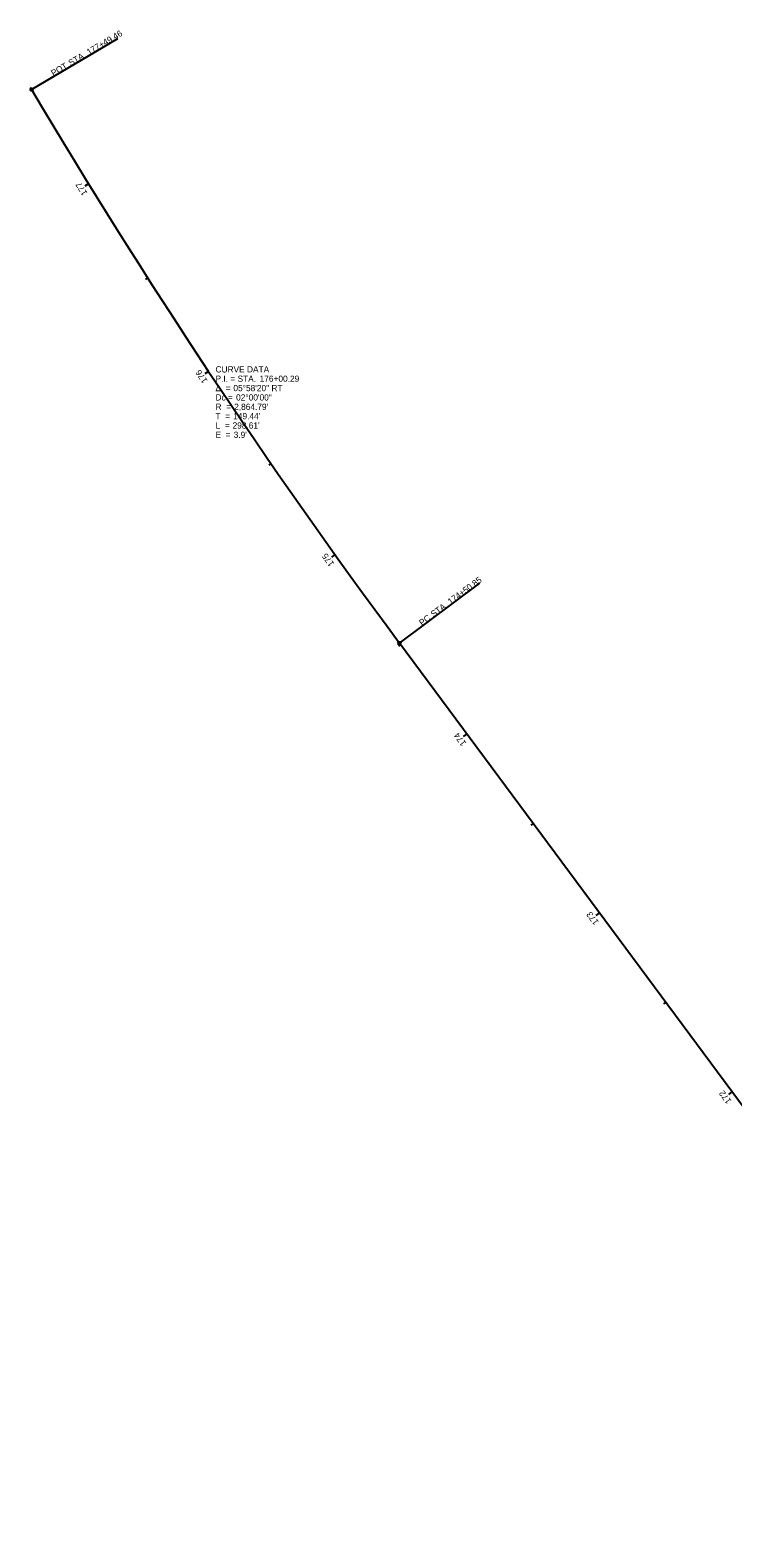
# Model space of a CAD drawing. Extents: x 142407 to 143428, y 484951 to 486303.
# Drawn here: x 142407 to 142723, y 485626 to 486303 of the extents above; entities that cross this region are included whole.
import ezdxf

# ---------------------------------------------------------------- set-up
doc = ezdxf.new("R2010")
doc.units = 0
for name, color, linetype in [('GE_X_Alignment', 7, 'Continuous'), ('GE_X_Alignment_1000_Curve_Data', 7, 'Continuous'), ('GE_X_Alignment_1000_Stations', 7, 'Continuous'), ('GE_X_Alignment_100_Curve_Data', 7, 'Continuous'), ('GE_X_Alignment_100_Stations', 7, 'Continuous'), ('GE_X_Alignment_500_Curve_Data', 7, 'Continuous'), ('GE_X_Alignment_500_Stations', 7, 'Continuous'), ('SV_P_Control_Cells_Set', 7, 'Continuous')]:
    doc.layers.add(name, color=color, linetype=linetype)

msp = doc.modelspace()

# ---------------------------------------------------------------- linework, layer by layer
at = {"layer": 'GE_X_Alignment'}
msp.add_line((143201.27, 485180.76), (142573.01, 486028.27), dxfattribs=at)
msp.add_arc((144872.98, 487736.23), 2864.79, 210.62525, 216.59745, dxfattribs=at)
at = {"layer": 'GE_X_Alignment_1000_Stations'}
for p, q in [((142407.78, 486276.85), (142446.51, 486299.77)), ((142544.04, 486067.98), (142543.07, 486067.28)), ((142573.01, 486028.27), (142609.13, 486055.1))]:
    msp.add_line(p, q, dxfattribs=at)
for centre in [(142407.78, 486276.85), (142573.01, 486028.27)]:
    msp.add_circle(centre, 0.6, dxfattribs=at)
at = {"layer": 'GE_X_Alignment_100_Stations'}
for p, q in [((142407.78, 486276.85), (142446.51, 486299.77)), ((142433.35, 486234.5), (142431.64, 486233.45)), ((142459.93, 486192.15), (142458.92, 486191.51)), ((142487.24, 486150.27), (142485.58, 486149.17)), ((142515.28, 486108.88), (142514.3, 486108.2)), ((142544.04, 486067.98), (142542.42, 486066.81)), ((142573.01, 486028.27), (142609.13, 486055.1)), ((142573.51, 486027.59), (142572.55, 486026.87)), ((142603.29, 485987.42), (142601.68, 485986.23)), ((142633.07, 485947.25), (142632.1, 485946.54)), ((142662.84, 485907.09), (142661.23, 485905.89)), ((142692.62, 485866.92), (142691.65, 485866.2)), ((142722.39, 485826.75), (142720.79, 485825.56))]:
    msp.add_line(p, q, dxfattribs=at)
for centre in [(142407.78, 486276.85), (142573.01, 486028.27)]:
    msp.add_circle(centre, 0.6, dxfattribs=at)
at = {"layer": 'GE_X_Alignment_500_Stations'}
for p, q in [((142407.78, 486276.85), (142446.51, 486299.77)), ((142433.35, 486234.5), (142432.32, 486233.87)), ((142487.24, 486150.27), (142486.24, 486149.61)), ((142544.04, 486067.98), (142542.42, 486066.81)), ((142573.01, 486028.27), (142609.13, 486055.1)), ((142603.29, 485987.42), (142602.33, 485986.71)), ((142662.84, 485907.09), (142661.88, 485906.37)), ((142722.39, 485826.75), (142721.43, 485826.04))]:
    msp.add_line(p, q, dxfattribs=at)
for centre in [(142407.78, 486276.85), (142573.01, 486028.27)]:
    msp.add_circle(centre, 0.6, dxfattribs=at)
at = {"layer": 'SV_P_Control_Cells_Set'}
for p, q in [((142408.45, 486276.18), (142407.11, 486277.51)), ((142407.11, 486276.18), (142408.45, 486277.51)), ((142573.67, 486027.61), (142572.34, 486028.94)), ((142572.34, 486027.61), (142573.67, 486028.94))]:
    msp.add_line(p, q, dxfattribs=at)

# ---------------------------------------------------------------- texts
at = {"layer": 'GE_X_Alignment_1000_Curve_Data'}
for s, p in [('CURVE DATA', (142490.39, 486149.76)), ('Δ  = ', (142490.39, 486141.36)), ('P.I. = STA. ', (142490.39, 486145.56)), ('05°58\'20" RT', (142498.42, 486141.36)), ('176+00.29', (142510.21, 486145.56)), ('Dc = ', (142490.39, 486137.16)), ('02°00\'00"', (142499.63, 486137.16)), ('T  = ', (142490.39, 486128.76)), ('R  = ', (142490.39, 486132.96)), ("149.44'", (142498.33, 486128.76)), ("2,864.79'", (142498.76, 486132.96)), ('L  = ', (142490.39, 486124.56)), ('E  = ', (142490.39, 486120.36)), ("298.61'", (142498.04, 486124.56)), ("3.9'", (142498.55, 486120.36))]:
    msp.add_text(s, height=2.8, dxfattribs=at).set_placement(p)
at = {"layer": 'GE_X_Alignment_1000_Stations'}
for s, rotation, p in [('177+49.46', 30.62525, (142433.57, 486292.17)), (' STA. ', 30.62525, (142424.46, 486286.78)), ('POT', 30.62525, (142417.54, 486282.68)), ('174+50.85', 36.59745, (142596, 486045.41)), (' STA. ', 36.59745, (142587.51, 486039.1)), ('PC', 36.59745, (142583.14, 486035.86))]:
    msp.add_text(s, height=2.8, rotation=rotation, dxfattribs=at).set_placement(p)
at = {"layer": 'GE_X_Alignment_100_Curve_Data'}
for s, p in [('CURVE DATA', (142490.39, 486149.76)), ('Δ  = ', (142490.39, 486141.36)), ('P.I. = STA. ', (142490.39, 486145.56)), ('05°58\'20" RT', (142498.42, 486141.36)), ('176+00.29', (142510.21, 486145.56)), ('Dc = ', (142490.39, 486137.16)), ('02°00\'00"', (142499.63, 486137.16)), ('T  = ', (142490.39, 486128.76)), ('R  = ', (142490.39, 486132.96)), ("149.44'", (142498.33, 486128.76)), ("2,864.79'", (142498.76, 486132.96)), ('L  = ', (142490.39, 486124.56)), ('E  = ', (142490.39, 486120.36)), ("298.61'", (142498.04, 486124.56)), ("3.9'", (142498.55, 486120.36))]:
    msp.add_text(s, height=2.8, dxfattribs=at).set_placement(p)
at = {"layer": 'GE_X_Alignment_100_Stations'}
for s, rotation, p in [('177+49.46', 30.62525, (142433.57, 486292.17)), (' STA. ', 30.62525, (142424.46, 486286.78)), ('POT', 30.62525, (142417.54, 486282.68)), ('177', 121.61454, (142433, 486230.27)), ('176', 123.61454, (142486.98, 486146.07)), ('175', 125.61454, (142543.9, 486063.81)), ('174+50.85', 36.59745, (142596, 486045.41)), (' STA. ', 36.59745, (142587.51, 486039.1)), ('PC', 36.59745, (142583.14, 486035.86)), ('174', 126.54954, (142603.22, 485983.3)), ('173', 126.54954, (142662.75, 485902.94)), ('172', 126.54954, (142722.33, 485822.62))]:
    msp.add_text(s, height=2.8, rotation=rotation, dxfattribs=at).set_placement(p)
at = {"layer": 'GE_X_Alignment_500_Curve_Data'}
for s, p in [('CURVE DATA', (142490.39, 486149.76)), ('Δ  = ', (142490.39, 486141.36)), ('P.I. = STA. ', (142490.39, 486145.56)), ('05°58\'20" RT', (142498.42, 486141.36)), ('176+00.29', (142510.21, 486145.56)), ('Dc = ', (142490.39, 486137.16)), ('02°00\'00"', (142499.63, 486137.16)), ('T  = ', (142490.39, 486128.76)), ('R  = ', (142490.39, 486132.96)), ("149.44'", (142498.33, 486128.76)), ("2,864.79'", (142498.76, 486132.96)), ('L  = ', (142490.39, 486124.56)), ('E  = ', (142490.39, 486120.36)), ("298.61'", (142498.04, 486124.56)), ("3.9'", (142498.55, 486120.36))]:
    msp.add_text(s, height=2.8, dxfattribs=at).set_placement(p)
at = {"layer": 'GE_X_Alignment_500_Stations'}
for s, rotation, p in [('177+49.46', 30.62525, (142433.57, 486292.17)), (' STA. ', 30.62525, (142424.46, 486286.78)), ('POT', 30.62525, (142417.54, 486282.68)), ('175', 125.61454, (142543.9, 486063.81)), ('174+50.85', 36.59745, (142596, 486045.41)), (' STA. ', 36.59745, (142587.51, 486039.1)), ('PC', 36.59745, (142583.14, 486035.86))]:
    msp.add_text(s, height=2.8, rotation=rotation, dxfattribs=at).set_placement(p)

doc.saveas('drawing.dxf')
